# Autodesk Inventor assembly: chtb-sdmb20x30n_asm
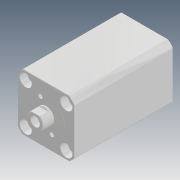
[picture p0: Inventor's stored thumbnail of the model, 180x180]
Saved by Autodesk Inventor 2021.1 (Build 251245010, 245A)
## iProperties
Company: Microsoft
Created: 2018-05
Part Number: chtb-sdmb20x30n_asm
Description: STEP AP214
Document SubType Name: Assembly
Designer: user
Title: chtb-sdmb20x30n_asm.STEP
Author: Windows
Revision Number: ÈÎºÎ
Sending System: SolidWorks 2015
Preprocessor: SwSTEP 2.0
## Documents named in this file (4)
- D:\Vault_2016\Projekty\Clamptek\Hydraulic\CHTB\CHTB-20\Inventor\CHTB-SDMB20x30N\chtb-sdmb20x30n_asm.iam
- D:\Vault_2016\Projekty\Clamptek\Hydraulic\CHTB\CHTB-20\Inventor\CHTB-SDMB20x30N\CHTB-SDMB20X30NBT.ipt
- D:\Vault_2016\Projekty\Clamptek\Hydraulic\CHTB\CHTB-20\Inventor\CHTB-SDMB20x30N\CHTB-SDMB20X30NHSG.ipt
- D:\Vault_2016\Projekty\Clamptek\Hydraulic\CHTB\CHTB-20\Inventor\CHTB-SDMB20x30N\QG_3.ipt
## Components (3 placed, 3 different names)
1. CHTB-SDMB20X30NBT_1
2. CHTB-SDMB20X30NHSG_2
3. QG_3_3
